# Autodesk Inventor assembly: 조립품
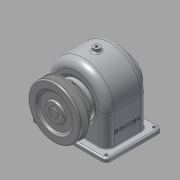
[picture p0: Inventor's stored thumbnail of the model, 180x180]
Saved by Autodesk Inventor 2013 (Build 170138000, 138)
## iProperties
Created: 2016-01
Part Number: 조립품
Document SubType Name: Assembly
Designer: dgall
Author: dgall
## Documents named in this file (16)
- C:\Users\dgall\Desktop\조립품.iam
- C:\Users\dgall\Desktop\본체.ipt
- C:\Users\dgall\Desktop\460105V1028\V-벨트풀리.ipt
- C:\Users\dgall\Desktop\460105V1028\뒤커버.ipt
- C:\Users\dgall\Desktop\460105V1028\멈춤나사 - M4x10.ipt
- C:\Users\dgall\Desktop\460105V1028\베어링 6203.ipt
- C:\Users\dgall\Desktop\460105V1028\볼트 M3 x 8.ipt
- C:\Users\dgall\Desktop\460105V1028\볼트 M3 x 10.ipt
- C:\Users\dgall\Desktop\460105V1028\부시1.ipt
- C:\Users\dgall\Desktop\460105V1028\부시2.ipt
- C:\Users\dgall\Desktop\460105V1028\스퍼기어.ipt
- C:\Users\dgall\Desktop\460105V1028\앞커버.ipt
- C:\Users\dgall\Desktop\460105V1028\오일씰 28 40 8.ipt
- C:\Users\dgall\Desktop\460105V1028\축.ipt
- C:\Users\dgall\Desktop\460105V1028\키 - 5 x 5 x 18.ipt
- C:\Users\dgall\Desktop\460105V1028\키 - 6 x 6 x 22.ipt
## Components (9 placed, 3 different names)
1. V-벨트풀리:1
2. ISO 4762 M3 x 8:1
3. ISO 4762 M3 x 10:1
4. ISO 4762 M3 x 10:2
5. ISO 4762 M3 x 10:3
6. ISO 4762 M3 x 10:4
7. ISO 4762 M3 x 8:2
8. ISO 4762 M3 x 8:3
9. ISO 4762 M3 x 8:4
